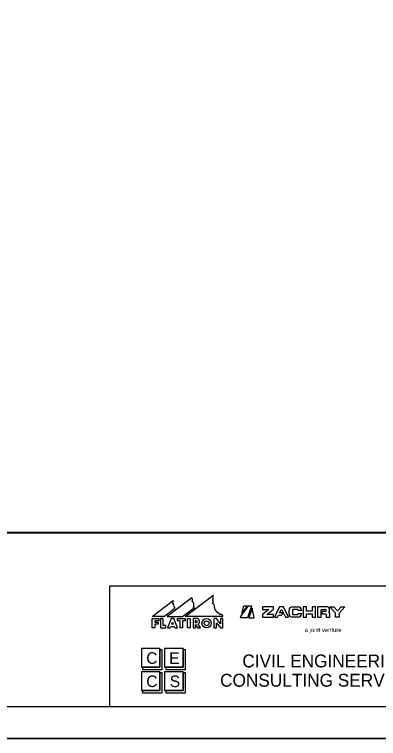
# Model space of a CAD drawing. Extents: x -2251 to 10196, y -13470 to 1199.
# Drawn here: x 3740 to 4022, y -2926 to -2363 of the extents above; entities that cross this region are included whole.
import ezdxf

# ---------------------------------------------------------------- set-up
doc = ezdxf.new("R2010")
doc.units = 0
for name, color, linetype in [('Level 3', 7, 'Continuous'), ('RD_SHT_Bndy', 7, 'Continuous'), ('RD_SHT_Iplotshp', 7, 'Continuous'), ('RD_SHT_Logo', 7, 'Continuous'), ('RD_SHT_Misc1', 7, 'Continuous'), ('RD_SHT_Snap', 7, 'Continuous'), ('RD_SHT_TX', 7, 'Continuous'), ('RD_TX_RoadID', 7, 'Continuous')]:
    doc.layers.add(name, color=color, linetype=linetype)

msp = doc.modelspace()

# ---------------------------------------------------------------- linework, layer by layer
at = {"layer": 'Level 3'}
msp.add_line((3965.07, -2863.99), (3965.07, -2863.99), dxfattribs=at)
msp.add_line((3965.07, -2863.99), (3965.07, -2863.99), dxfattribs=at)
msp.add_line((3965.07, -2863.99), (3965.07, -2863.99), dxfattribs=at)
msp.add_line((3965.07, -2863.99), (3965.07, -2863.99), dxfattribs=at)
at = {"layer": 'RD_SHT_Bndy'}
for p, q in [((2603.1, -2900.65), (4278.1, -2900.65)), ((4291.65, -2925.65), (2531.65, -2925.65))]:
    msp.add_line(p, q, dxfattribs=at)
msp.add_lwpolyline([(2653.4, -1901.26), (4231.08, -1901.26), (4231.08, -2765.57), (2653.4, -2765.57)], close=True, dxfattribs=at)
at = {"layer": 'RD_SHT_Iplotshp'}
msp.add_lwpolyline([(2496.65, -1825.65), (4296.65, -1825.65), (4296.65, -2925.65), (2496.65, -2925.65)], close=True, dxfattribs=at)
at = {"layer": 'RD_SHT_Logo'}
for p, q in [((3877.35, -2816.27), (3858.31, -2830.86)), ((3872.32, -2830.86), (3893.74, -2814.44)), ((3846.7, -2830.86), (3862.98, -2818.38)), ((3915.56, -2830.77), (3921.47, -2822.59)), ((3920.48, -2822.59), (3916.24, -2828.47)), ((3916.24, -2828.47), (3917.96, -2822.59)), ((3917.96, -2822.59), (3920.48, -2822.59)), ((3923.82, -2822.59), (3920.68, -2831.76)), ((3921.47, -2822.59), (3923.82, -2822.59)), ((3940.93, -2823.35), (3932.22, -2823.35)), ((3932.22, -2823.35), (3932.22, -2825.3)), ((3940.93, -2825.16), (3940.93, -2823.35)), ((3945.58, -2823.35), (3941.53, -2831.3)), ((3948.58, -2823.35), (3945.58, -2823.35)), ((3952.63, -2831.3), (3948.58, -2823.35)), ((3955.44, -2823.35), (3960.18, -2823.35)), ((3966.62, -2823.35), (3964.02, -2823.35)), ((3964.02, -2823.35), (3964.02, -2831.3)), ((3966.62, -2826.8), (3966.62, -2823.35)), ((3970.9, -2823.35), (3970.9, -2826.8)), ((3973.51, -2823.35), (3970.9, -2823.35)), ((3973.5, -2831.3), (3973.51, -2823.35)), ((3982.43, -2823.35), (3975.13, -2823.35)), ((3975.13, -2823.35), (3975.13, -2831.3)), ((3984.68, -2823.35), (3987.64, -2823.35)), ((3989.08, -2828.24), (3984.68, -2823.35)), ((3987.64, -2823.35), (3990.48, -2826.51)), ((3990.48, -2826.51), (3993.32, -2823.35)), ((3996.28, -2823.35), (3991.88, -2828.24)), ((3993.32, -2823.35), (3996.28, -2823.35)), ((3864.27, -2824.74), (3856.29, -2830.86)), ((3870.3, -2830.86), (3879.48, -2823.82)), ((3924.24, -2824.44), (3921.74, -2831.76)), ((3925.99, -2831.76), (3924.24, -2824.44)), ((3937.2, -2825.3), (3932.22, -2829.24)), ((3932.22, -2825.3), (3937.2, -2825.3)), ((3932.22, -2829.24), (3932.22, -2831.3)), ((3935.63, -2829.35), (3940.93, -2825.16)), ((3940.93, -2829.35), (3935.63, -2829.35)), ((3940.93, -2831.3), (3940.93, -2829.35)), ((3945.57, -2827.99), (3946.71, -2825.75)), ((3948.15, -2827.99), (3945.57, -2827.99)), ((3946.71, -2825.75), (3947.44, -2825.75)), ((3947.23, -2829.79), (3948.15, -2827.99)), ((3947.44, -2825.75), (3950.27, -2831.3)), ((3952.94, -2828.8), (3952.94, -2825.85)), ((3955.64, -2825.8), (3955.64, -2828.85)), ((3959.48, -2825.3), (3956.14, -2825.3)), ((3956.14, -2829.35), (3959.48, -2829.35)), ((3959.98, -2826.15), (3959.98, -2825.8)), ((3962.68, -2826.15), (3959.98, -2826.15)), ((3959.98, -2828.5), (3962.68, -2828.5)), ((3959.98, -2828.85), (3959.98, -2828.5)), ((3962.68, -2825.85), (3962.68, -2826.15)), ((3962.68, -2828.5), (3962.68, -2828.8)), ((3970.9, -2826.8), (3966.62, -2826.8)), ((3966.62, -2831.3), (3966.62, -2828.8)), ((3966.62, -2828.8), (3970.9, -2828.8)), ((3970.9, -2828.8), (3970.9, -2831.3)), ((3977.83, -2831.3), (3977.83, -2825.31)), ((3977.83, -2825.31), (3981.07, -2825.31)), ((3979.03, -2826.97), (3978.11, -2828.77)), ((3978.11, -2828.77), (3981.24, -2828.77)), ((3981.07, -2826.97), (3979.03, -2826.97)), ((3981.74, -2829.27), (3981.74, -2831.3)), ((3983.68, -2827.6), (3983.68, -2827.47)), ((3984.43, -2826.36), (3984.43, -2825.35)), ((3984.54, -2831.3), (3984.54, -2828.76)), ((3989.08, -2831.3), (3989.08, -2828.24)), ((3991.88, -2828.24), (3991.88, -2831.3)), ((3856.29, -2830.86), (3846.7, -2830.86)), ((3846.72, -2839.7), (3846.72, -2832.5)), ((3846.72, -2832.5), (3851.82, -2832.5)), ((3851.82, -2834.15), (3848.67, -2834.15)), ((3848.67, -2834.15), (3848.67, -2835.21)), ((3851.82, -2832.5), (3851.82, -2834.15)), ((3855.12, -2832.5), (3853.17, -2832.5)), ((3853.17, -2832.5), (3853.17, -2839.7)), ((3855.12, -2837.9), (3855.12, -2832.5)), ((3858.31, -2830.86), (3870.3, -2830.86)), ((3861.42, -2832.5), (3858.65, -2839.71)), ((3863.52, -2832.5), (3861.42, -2832.5)), ((3866.28, -2839.71), (3863.52, -2832.5)), ((3866.22, -2834.15), (3866.22, -2832.5)), ((3866.22, -2832.5), (3872.37, -2832.5)), ((3868.32, -2834.15), (3866.22, -2834.15)), ((3868.32, -2839.71), (3868.32, -2834.15)), ((3872.37, -2834.15), (3870.27, -2834.15)), ((3870.27, -2834.15), (3870.27, -2839.71)), ((3901.19, -2830.86), (3872.32, -2830.86)), ((3872.37, -2832.5), (3872.37, -2834.15)), ((3874.17, -2839.71), (3874.17, -2832.5)), ((3874.17, -2832.5), (3876.12, -2832.5)), ((3876.12, -2832.5), (3876.12, -2839.71)), ((3881.8, -2832.5), (3878.38, -2832.5)), ((3878.38, -2832.5), (3878.38, -2839.71)), ((3880.33, -2835.66), (3880.33, -2834.01)), ((3896.52, -2832.5), (3894.57, -2832.5)), ((3894.57, -2832.5), (3894.57, -2839.71)), ((3899.67, -2836.53), (3896.52, -2832.5)), ((3901.62, -2832.5), (3899.67, -2832.5)), ((3899.67, -2832.5), (3899.67, -2836.53)), ((3901.62, -2839.71), (3901.62, -2832.5)), ((3915.27, -2831.76), (3915.56, -2830.77)), ((3920.68, -2831.76), (3915.27, -2831.76)), ((3921.74, -2831.76), (3925.99, -2831.76)), ((3932.22, -2831.3), (3940.93, -2831.3)), ((3941.53, -2831.3), (3943.88, -2831.3)), ((3943.88, -2831.3), (3944.65, -2829.79)), ((3944.65, -2829.79), (3947.23, -2829.79)), ((3950.27, -2831.3), (3952.63, -2831.3)), ((3960.18, -2831.3), (3955.44, -2831.3)), ((3964.02, -2831.3), (3966.62, -2831.3)), ((3970.9, -2831.3), (3973.5, -2831.3)), ((3975.13, -2831.3), (3977.83, -2831.3)), ((3981.74, -2831.3), (3984.54, -2831.3)), ((3991.88, -2831.3), (3989.08, -2831.3)), ((3848.67, -2839.7), (3846.72, -2839.7)), ((3848.67, -2835.21), (3851.22, -2835.21)), ((3851.22, -2836.86), (3848.67, -2836.86)), ((3848.67, -2836.86), (3848.67, -2839.7)), ((3851.22, -2835.21), (3851.22, -2836.86)), ((3853.17, -2839.7), (3857.37, -2839.71)), ((3857.37, -2837.9), (3855.12, -2837.9)), ((3857.37, -2839.71), (3857.37, -2837.9)), ((3858.65, -2839.71), (3860.74, -2839.71)), ((3860.74, -2839.71), (3861.2, -2838.51)), ((3861.2, -2838.51), (3863.74, -2838.51)), ((3861.83, -2836.86), (3862.47, -2835.2)), ((3863.1, -2836.86), (3861.83, -2836.86)), ((3862.47, -2835.2), (3863.1, -2836.86)), ((3863.74, -2838.51), (3864.2, -2839.71)), ((3864.2, -2839.71), (3866.28, -2839.71)), ((3870.27, -2839.71), (3868.32, -2839.71)), ((3876.12, -2839.71), (3874.17, -2839.71)), ((3878.38, -2839.71), (3880.33, -2839.71)), ((3880.33, -2839.71), (3880.33, -2837.02)), ((3880.33, -2837.02), (3881.94, -2839.71)), ((3881.94, -2839.71), (3884.16, -2839.71)), ((3884.16, -2839.71), (3882.43, -2836.82)), ((3894.57, -2839.71), (3896.52, -2839.71)), ((3896.52, -2839.71), (3896.52, -2835.67)), ((3896.52, -2835.67), (3899.67, -2839.71)), ((3899.67, -2839.71), (3901.62, -2839.71)), ((3852.67, -2855.79), (3838.28, -2855.79)), ((3838.28, -2855.79), (3838.28, -2870.23)), ((3852.67, -2870.23), (3852.67, -2855.79)), ((3852.67, -2855.79), (3852.67, -2870.23)), ((3854.48, -2856.7), (3852.67, -2856.7)), ((3854.48, -2872.03), (3854.48, -2856.7)), ((3870.67, -2855.79), (3856.27, -2855.79)), ((3856.27, -2855.79), (3856.27, -2870.23)), ((3870.67, -2870.23), (3870.67, -2855.79)), ((3870.67, -2855.79), (3870.67, -2870.23)), ((3872.48, -2856.7), (3870.67, -2856.7)), ((3872.48, -2872.03), (3872.48, -2856.7)), ((3838.28, -2870.23), (3852.67, -2870.23)), ((3852.67, -2873.84), (3838.28, -2873.84)), ((3838.28, -2873.84), (3838.28, -2888.27)), ((3852.67, -2870.23), (3839.17, -2870.23)), ((3839.17, -2870.23), (3839.17, -2872.03)), ((3839.17, -2872.03), (3854.48, -2872.03)), ((3852.67, -2888.27), (3852.67, -2873.84)), ((3852.67, -2873.84), (3852.67, -2888.27)), ((3856.27, -2870.23), (3870.67, -2870.23)), ((3870.67, -2873.84), (3856.27, -2873.84)), ((3856.27, -2873.84), (3856.27, -2888.27)), ((3870.67, -2870.23), (3857.18, -2870.23)), ((3857.18, -2870.23), (3857.18, -2872.03)), ((3857.18, -2872.03), (3872.48, -2872.03)), ((3870.67, -2888.27), (3870.67, -2873.84)), ((3870.67, -2873.84), (3870.67, -2888.27)), ((3854.48, -2874.74), (3852.67, -2874.74)), ((3854.48, -2890.07), (3854.48, -2874.74)), ((3872.48, -2874.74), (3870.67, -2874.74)), ((3872.48, -2890.07), (3872.48, -2874.74)), ((3838.28, -2888.27), (3852.67, -2888.27)), ((3852.67, -2888.27), (3839.17, -2888.27)), ((3839.17, -2888.27), (3839.17, -2890.07)), ((3839.17, -2890.07), (3854.48, -2890.07)), ((3856.27, -2888.27), (3870.67, -2888.27)), ((3870.67, -2888.27), (3857.18, -2888.27)), ((3857.18, -2888.27), (3857.18, -2890.07)), ((3857.18, -2890.07), (3872.48, -2890.07))]:
    msp.add_line(p, q, dxfattribs=at)
for radius in [3.6, 1.9]:
    msp.add_circle((3888.95, -2836.1), radius, dxfattribs=at)
for centre, radius, start, end in [((3875.05, -2818.02), 2.89, 342.0343, 37.2653), ((3893.13, -2817.66), 0.749, 309.4079, 17.0499), ((3897.87, -2816.34), 4.17, 156.4699, 195.3053), ((3893.86, -2814.6), 0.2, 336.4699, 127.4657), ((3866.29, -2820.12), 3.74, 152.2252, 185.8662), ((3862.1, -2821.62), 1.21, 351.6466, 67.1294), ((3864.29, -2821.94), 1, 171.6466, 221.9371), ((3863.11, -2823.01), 0.592, 327.6019, 41.9371), ((3863.3, -2824.33), 1.05, 337.4201, 73.1261), ((3877.99, -2818.97), 0.2, 162.0343, 220.8638), ((3876.86, -2819.95), 1.3, 11.8745, 40.8638), ((3878.32, -2819.64), 0.2, 191.8745, 279.8173), ((3878.44, -2820.33), 0.499, 44.4799, 99.8173), ((3875.8, -2822.18), 3.16, 331.2486, 18.4584), ((3878.92, -2824.44), 0.827, 48.0701, 115.7229), ((3879.5, -2820.72), 0.843, 144.641, 212.5499), ((3878.65, -2820.12), 0.2, 324.641, 44.4799), ((3893.57, -2820.5), 0.2, 133.0036, 262.3069), ((3891.59, -2818.37), 2.7, 313.0036, 343.6807), ((3893.73, -2818.39), 0.2, 129.4079, 246.863), ((3893.31, -2822.44), 1.76, 45.283, 82.3069), ((3893.27, -2819.47), 0.973, 20.4113, 66.863), ((3894.4, -2821.33), 0.2, 353.8329, 45.283), ((3901.36, -2822.08), 6.8, 173.8329, 242.3928), ((3955.44, -2825.85), 2.5, 89.9984, 179.9984), ((3960.18, -2825.85), 2.5, 359.9984, 89.9984), ((3982.43, -2825.35), 2, 359.9984, 89.9984), ((3898.12, -2828.28), 0.2, 9.0833, 62.3928), ((3899.35, -2828.09), 1.04, 189.0833, 295.769), ((3899.89, -2829.21), 0.2, 33.7112, 115.769), ((3900.89, -2828.54), 1.01, 213.7112, 268.6299), ((3955.44, -2828.8), 2.5, 179.9984, 269.9984), ((3956.14, -2825.8), 0.5, 89.9984, 179.9984), ((3956.14, -2828.85), 0.5, 179.9984, 269.9984), ((3959.48, -2825.8), 0.5, 359.9984, 89.9984), ((3959.48, -2828.85), 0.5, 269.9984, 359.9984), ((3960.18, -2828.8), 2.5, 269.9984, 359.9984), ((3981.07, -2826.14), 0.831, 269.9984, 89.9984), ((3981.24, -2829.27), 0.5, 359.9984, 89.9984), ((3983.23, -2826.36), 1.2, 291.95, 359.9984), ((3983.34, -2828.76), 1.2, 359.9984, 73.7977), ((3900.86, -2829.74), 0.2, 78.9712, 88.6299), ((3900.75, -2830.3), 0.767, 320.912, 78.9712), ((3901.19, -2830.66), 0.2, 269.9984, 320.912)]:
    msp.add_arc(centre, radius, start, end, dxfattribs=at)
msp.add_ellipse((3880.33, -2834.83), major_axis=(1.36, 0), ratio=0.609965, start_param=4.712389, end_param=7.853982, dxfattribs=at)
msp.add_open_spline([(3882.43, -2836.82), (3882.51, -2836.76), (3882.59, -2836.7), (3882.81, -2836.49), (3882.95, -2836.34), (3883.13, -2836.07), (3883.19, -2835.97), (3883.29, -2835.77), (3883.34, -2835.66), (3883.41, -2835.44), (3883.44, -2835.32), (3883.47, -2835.08), (3883.48, -2834.96), (3883.48, -2834.71), (3883.47, -2834.59), (3883.44, -2834.35), (3883.41, -2834.23), (3883.34, -2834.01), (3883.29, -2833.9), (3883.19, -2833.7), (3883.13, -2833.6), (3882.95, -2833.33), (3882.81, -2833.18), (3882.52, -2832.91), (3882.37, -2832.8), (3882.08, -2832.63), (3881.94, -2832.56), (3881.8, -2832.5)], degree=3, dxfattribs=at)
at = {"layer": 'RD_SHT_Misc1'}
msp.add_lwpolyline([(4296.65, -2925.65), (4296.68, -1825.65), (2596.68, -1825.6), (2596.65, -2925.6)], close=True, dxfattribs=at)
at = {"layer": 'RD_SHT_Snap'}
msp.add_lwpolyline([(2508.15, -1825.65), (4308.15, -1825.65), (4308.15, -2925.65), (2508.15, -2925.65)], close=True, dxfattribs=at)
at = {"layer": 'RD_SHT_TX'}
for p, q in [((3813.76, -2900.65), (3813.76, -2807.15)), ((3813.76, -2900.65), (3813.76, -2807.15)), ((3813.76, -2807.15), (4278.1, -2807.15))]:
    msp.add_line(p, q, dxfattribs=at)
at = {"layer": 'RD_TX_RoadID'}
msp.add_lwpolyline([(2650.54, -2765.73), (4233.93, -2765.73), (4233.93, -1962.61), (2650.54, -1962.61)], close=True, dxfattribs=at)

# ---------------------------------------------------------------- texts
at = {"layer": 'RD_SHT_Logo'}
msp.add_text('a joint venture', height=3.3, rotation=359.9984, dxfattribs=at).set_placement((3965.08, -2842.93))
for s, height, p in [('C', 9.02, (3842.11, -2867.66)), ('E', 9.02, (3859.9, -2867.66)), ('CIVIL ENGINEERING', 10, (3916.67, -2870.38)), ('C', 9.02, (3842.11, -2885.71)), ('S', 9.02, (3860.32, -2885.71)), ('CONSULTING SERVICES, INC.', 10, (3899.39, -2885.38))]:
    msp.add_text(s, height=height, dxfattribs=at).set_placement(p)

doc.saveas('drawing.dxf')
